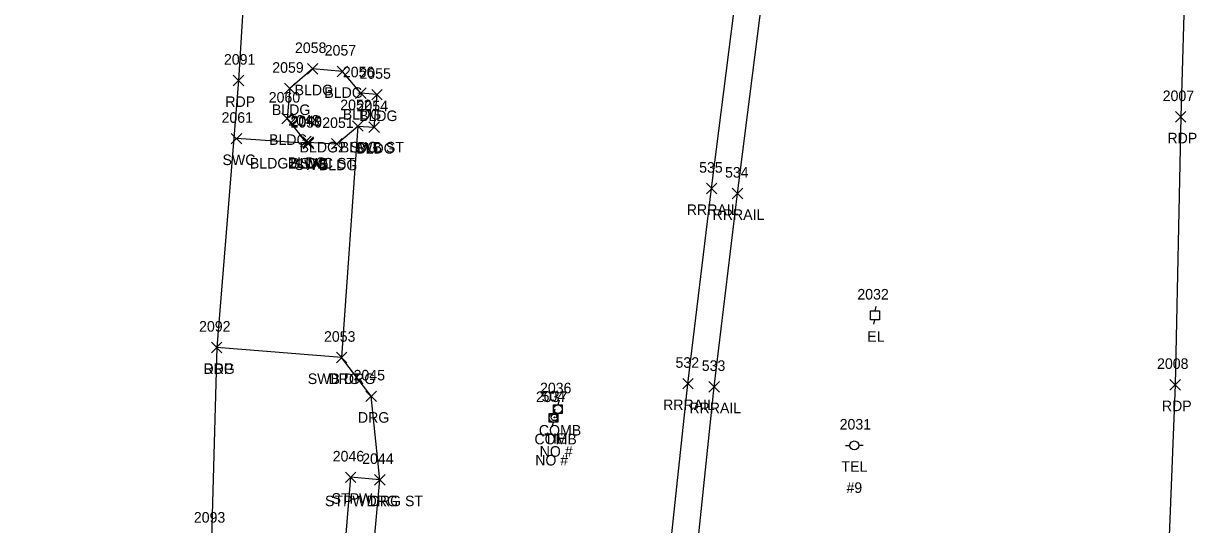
# Model space of a CAD drawing. Extents: x 1767353 to 1772625, y 740790 to 747702.
# Drawn here: x 1770045.2 to 1770267.3, y 741671.2 to 741766 of the extents above; entities that cross this region are included whole.
import ezdxf

# ---------------------------------------------------------------- set-up
doc = ezdxf.new("R2010")
doc.units = 0
for name, color, linetype in [('C_A', 7, 'Continuous'), ('C_I', 7, 'Continuous'), ('CBP', 7, 'Continuous'), ('L_A', 7, 'Continuous'), ('L_I', 7, 'Continuous'), ('L_TIC', 7, 'Continuous'), ('LBC', 7, 'Continuous'), ('LBF', 7, 'Continuous'), ('P_A', 7, 'Continuous'), ('P_I', 7, 'Continuous'), ('P_TIC', 7, 'Continuous'), ('PET', 7, 'Continuous'), ('R_A', 7, 'Continuous'), ('R_I', 7, 'Continuous'), ('R_TIC', 7, 'Continuous'), ('RDG', 7, 'Continuous'), ('RR', 7, 'Continuous'), ('RSW', 7, 'Continuous'), ('U_A', 7, 'Continuous'), ('U_C', 7, 'Continuous'), ('U_I', 7, 'Continuous'), ('UEPT', 7, 'Continuous'), ('UP', 7, 'Continuous')]:
    doc.layers.add(name, color=color, linetype=linetype)

msp = doc.modelspace()

# ---------------------------------------------------------------- linework, layer by layer
at = {"layer": 'CBP'}
for radius in [0.625, 0.0833]:
    msp.add_circle((1770145.73, 741691.51), radius, dxfattribs=at)
at = {"layer": 'L_TIC'}
for points in [[(1770098.93, 741756.44), (1770100.93, 741758.44)], [(1770100.93, 741756.44), (1770098.93, 741758.44)], [(1770104.56, 741755.96), (1770106.56, 741757.96)], [(1770106.56, 741755.96), (1770104.56, 741757.96)], [(1770094.63, 741752.71), (1770096.63, 741754.71)], [(1770096.63, 741752.71), (1770094.63, 741754.71)], [(1770108.05, 741751.85), (1770110.05, 741753.85)], [(1770110.05, 741751.85), (1770108.05, 741753.85)], [(1770111.13, 741751.57), (1770113.13, 741753.57)], [(1770113.13, 741751.57), (1770111.13, 741753.57)], [(1770094.09, 741747.06), (1770096.09, 741749.06)], [(1770096.09, 741747.06), (1770094.09, 741749.06)], [(1770094.09, 741747.06), (1770096.09, 741749.06)], [(1770096.09, 741747.06), (1770094.09, 741749.06)], [(1770107.49, 741745.63), (1770109.49, 741747.63)], [(1770109.49, 741745.63), (1770107.49, 741747.63)], [(1770110.59, 741745.42), (1770112.59, 741747.42)], [(1770112.59, 741745.42), (1770110.59, 741747.42)], [(1770097.66, 741742.7), (1770099.66, 741744.7)], [(1770099.66, 741742.7), (1770097.66, 741744.7)], [(1770097.66, 741742.7), (1770099.66, 741744.7)], [(1770099.66, 741742.7), (1770097.66, 741744.7)], [(1770098.08, 741742.59), (1770100.08, 741744.59)], [(1770100.08, 741742.59), (1770098.08, 741744.59)], [(1770103.53, 741742.26), (1770105.53, 741744.26)], [(1770105.53, 741742.26), (1770103.53, 741744.26)], [(1770106.13, 741679.16), (1770108.13, 741681.16)], [(1770108.13, 741679.16), (1770106.13, 741681.16)], [(1770111.66, 741678.69), (1770113.66, 741680.69)], [(1770113.66, 741678.69), (1770111.66, 741680.69)]]:
    msp.add_lwpolyline(points, dxfattribs=at)
at = {"layer": 'LBC'}
for points in [[(1770098.66, 741743.7), (1770099.08, 741743.59), (1770104.53, 741743.26), (1770108.49, 741746.63), (1770111.59, 741746.42), (1770112.13, 741752.57), (1770109.05, 741752.85), (1770105.56, 741756.96), (1770099.93, 741757.44), (1770095.63, 741753.71), (1770095.09, 741748.06)], [(1770098.66, 741743.7), (1770095.09, 741748.06)]]:
    msp.add_lwpolyline(points, dxfattribs=at)
at = {"layer": 'LBF'}
msp.add_lwpolyline([(1770109.99, 741650.55), (1770112.66, 741679.69), (1770107.13, 741680.16), (1770104.69, 741650.97)], dxfattribs=at)
at = {"layer": 'P_TIC'}
for points in [[(1770084.91, 741754.24), (1770086.91, 741756.24)], [(1770086.91, 741754.24), (1770084.91, 741756.24)], [(1770263.31, 741747.35), (1770265.31, 741749.35)], [(1770265.31, 741747.35), (1770263.31, 741749.35)], [(1770080.77, 741703.72), (1770082.77, 741705.72)], [(1770082.77, 741703.72), (1770080.77, 741705.72)], [(1770262.25, 741696.67), (1770264.25, 741698.67)], [(1770264.25, 741696.67), (1770262.25, 741698.67)]]:
    msp.add_lwpolyline(points, dxfattribs=at)
at = {"layer": 'PET'}
for points in [[(1770086.36, 741896.23), (1770087.49, 741787.65), (1770087.53, 741783.15), (1770087.13, 741775.79), (1770085.91, 741755.24), (1770081.77, 741704.72), (1770080.78, 741668.58), (1770077.45, 741606.56), (1770073.71, 741567.99), (1770067.82, 741517.29), (1770065.02, 741495.1), (1770064.65, 741473.85), (1770058.3, 741423.48), (1770050.58, 741368.28), (1770045.18, 741323.67)], [(1770229.78, 741893.6), (1770250.07, 741887.1), (1770256.68, 741881.35), (1770263.49, 741873.94), (1770265.43, 741863.52), (1770266.15, 741845.69), (1770265.98, 741804.45), (1770264.31, 741748.35), (1770263.25, 741697.67), (1770261.51, 741653.19), (1770259.69, 741610.34)]]:
    msp.add_lwpolyline(points, dxfattribs=at)
at = {"layer": 'R_TIC'}
for points in [[(1770107.49, 741745.63), (1770109.49, 741747.63)], [(1770109.49, 741745.63), (1770107.49, 741747.63)], [(1770084.51, 741743.24), (1770086.51, 741745.24)], [(1770086.51, 741743.24), (1770084.51, 741745.24)], [(1770098.08, 741742.59), (1770100.08, 741744.59)], [(1770100.08, 741742.59), (1770098.08, 741744.59)], [(1770098.17, 741742.33), (1770100.17, 741744.33)], [(1770100.17, 741742.33), (1770098.17, 741744.33)], [(1770174.49, 741733.8), (1770176.49, 741735.8)], [(1770176.49, 741733.8), (1770174.49, 741735.8)], [(1770179.38, 741732.87), (1770181.38, 741734.87)], [(1770181.38, 741732.87), (1770179.38, 741734.87)], [(1770080.77, 741703.72), (1770082.77, 741705.72)], [(1770082.77, 741703.72), (1770080.77, 741705.72)], [(1770104.43, 741701.81), (1770106.43, 741703.81)], [(1770106.43, 741701.81), (1770104.43, 741703.81)], [(1770104.43, 741701.81), (1770106.43, 741703.81)], [(1770106.43, 741701.81), (1770104.43, 741703.81)], [(1770170.01, 741696.88), (1770172.01, 741698.88)], [(1770172.01, 741696.88), (1770170.01, 741698.88)], [(1770110.03, 741694.49), (1770112.03, 741696.49)], [(1770112.03, 741694.49), (1770110.03, 741696.49)], [(1770174.98, 741696.29), (1770176.98, 741698.29)], [(1770176.98, 741696.29), (1770174.98, 741698.29)], [(1770111.66, 741678.69), (1770113.66, 741680.69)], [(1770113.66, 741678.69), (1770111.66, 741680.69)]]:
    msp.add_lwpolyline(points, dxfattribs=at)
at = {"layer": 'RDG'}
msp.add_lwpolyline([(1770112.66, 741679.69), (1770111.03, 741695.49), (1770105.43, 741702.81), (1770081.77, 741704.72)], dxfattribs=at)
at = {"layer": 'RR'}
for points in [[(1770158.18, 741192.17), (1770156.33, 741234.55), (1770154.66, 741279.77), (1770153.5, 741326.69), (1770153.07, 741379.82), (1770153.42, 741422.94), (1770154.43, 741466.02), (1770156.03, 741508.16), (1770157.87, 741545.07), (1770160.69, 741586.39), (1770163.59, 741622.82), (1770166.84, 741658.9), (1770171.01, 741697.88), (1770175.49, 741734.8), (1770180.59, 741775.05), (1770185.91, 741810.5), (1770192.47, 741851.32), (1770197.89, 741882.78), (1770201.13, 741901.96), (1770208.66, 741941.8), (1770211.54, 741956.24), (1770217.02, 741983.21), (1770222.11, 742006.18)], [(1770163.08, 741192.31), (1770161.21, 741234.64), (1770159.62, 741280.6), (1770158.4, 741326.37), (1770158.03, 741379.87), (1770158.37, 741422.76), (1770159.48, 741466.41), (1770160.97, 741507.07), (1770162.92, 741544.79), (1770165.6, 741585.33), (1770168.59, 741623.26), (1770171.89, 741657.97), (1770175.98, 741697.29), (1770180.38, 741733.87), (1770185.58, 741774.59), (1770190.55, 741808.84), (1770197.31, 741850.84), (1770202.43, 741880.83), (1770205.99, 741900.79), (1770213.55, 741940.61), (1770216.39, 741955.4), (1770221.78, 741982.04), (1770226.9, 742005.14)]]:
    msp.add_lwpolyline(points, dxfattribs=at)
at = {"layer": 'RSW'}
for points in [[(1770108.49, 741746.63), (1770105.43, 741702.81)], [(1770099.08, 741743.59), (1770099.17, 741743.33), (1770085.51, 741744.24)]]:
    msp.add_lwpolyline(points, dxfattribs=at)
at = {"layer": 'UEPT'}
for p, q in [((1770206.59, 741712.46), (1770206.42, 741711.63)), ((1770205.59, 741709.96), (1770205.59, 741711.63)), ((1770205.59, 741711.63), (1770207.25, 741711.63)), ((1770207.25, 741709.96), (1770205.59, 741709.96)), ((1770206.17, 741709.13), (1770206.42, 741709.96)), ((1770206.42, 741710.8), (1770206.42, 741710.8)), ((1770207.25, 741711.63), (1770207.25, 741709.96))]:
    msp.add_line(p, q, dxfattribs=at)
at = {"layer": 'UP'}
for p, q in [((1770146.63, 741694.73), (1770146.38, 741693.9)), ((1770144.71, 741690.57), (1770144.71, 741692.24)), ((1770144.71, 741692.24), (1770146.38, 741692.24)), ((1770145.55, 741692.23), (1770145.55, 741693.9)), ((1770145.55, 741693.9), (1770147.21, 741693.9)), ((1770145.8, 741693.07), (1770145.55, 741692.24)), ((1770147.21, 741692.23), (1770145.55, 741692.23)), ((1770146.13, 741691.4), (1770146.38, 741692.23)), ((1770146.38, 741693.06), (1770146.38, 741693.06)), ((1770146.38, 741692.24), (1770146.38, 741690.57)), ((1770147.21, 741693.9), (1770147.21, 741692.23)), ((1770146.38, 741690.57), (1770144.71, 741690.57)), ((1770145.3, 741689.74), (1770145.55, 741690.57)), ((1770145.55, 741691.4), (1770145.55, 741691.4)), ((1770200.84, 741686.2), (1770201.66, 741686.2)), ((1770202.5, 741686.2), (1770202.5, 741686.2)), ((1770204.16, 741686.2), (1770203.33, 741686.2)), ((1770203.33, 741686.2), (1770203.33, 741686.2)), ((1770204.16, 741686.2), (1770204.16, 741686.2))]:
    msp.add_line(p, q, dxfattribs=at)
for centre in [(1770145.55, 741691.4), (1770146.38, 741693.06), (1770202.5, 741686.2)]:
    msp.add_circle(centre, 0.833, dxfattribs=at)

# ---------------------------------------------------------------- texts
at = {"layer": 'C_A'}
msp.add_text('TIE', height=2, dxfattribs=at).set_placement((1770143.8, 741686.51))
at = {"layer": 'C_I'}
msp.add_text('504', height=2, dxfattribs=at).set_placement((1770143.29, 741694.51))
at = {"layer": 'L_A'}
for s, p in [('BLDG', (1770096.52, 741752.44)), ('BLDG', (1770102.15, 741751.96)), ('BLDG', (1770092.22, 741748.71)), ('BLDG', (1770105.65, 741747.85)), ('BLDG', (1770108.72, 741747.57)), ('BLDG', (1770091.68, 741743.06)), ('BLDG', (1770091.68, 741743.06)), ('BLDG', (1770105.08, 741741.63)), ('BLDG', (1770108.18, 741741.42)), ('BLDG', (1770095.25, 741738.7)), ('BLDG', (1770095.25, 741738.7)), ('BLDG', (1770095.67, 741738.59)), ('BLDG', (1770101.12, 741738.26)), ('STPW DRG ST', (1770102.27, 741674.69)), ('STPW', (1770103.52, 741675.16))]:
    msp.add_text(s, height=2, dxfattribs=at).set_placement(p)
at = {"layer": 'L_I'}
for s, p in [('2058', (1770096.59, 741760.44)), ('2057', (1770102.22, 741759.96)), ('2059', (1770092.29, 741756.71)), ('2056', (1770105.66, 741755.85)), ('2055', (1770108.8, 741755.57)), ('2060', (1770091.62, 741751.06)), ('2060', (1770091.62, 741751.06)), ('2052', (1770105.16, 741749.63)), ('2054', (1770108.25, 741749.42)), ('2048', (1770095.32, 741746.7)), ('2048', (1770095.32, 741746.7)), ('2049', (1770095.74, 741746.59)), ('2051', (1770101.75, 741746.26)), ('2046', (1770103.74, 741683.16)), ('2044', (1770109.32, 741682.69))]:
    msp.add_text(s, height=2, dxfattribs=at).set_placement(p)
at = {"layer": 'P_A'}
for p in [(1770083.4, 741750.24), (1770261.8, 741743.35), (1770079.25, 741699.72), (1770260.74, 741692.67)]:
    msp.add_text('RDP', height=2, dxfattribs=at).set_placement(p)
at = {"layer": 'P_I'}
for s, p in [('2091', (1770083.14, 741758.24)), ('2007', (1770260.9, 741751.35)), ('2092', (1770078.43, 741707.72)), ('2008', (1770259.83, 741700.67)), ('2093', (1770077.44, 741671.58))]:
    msp.add_text(s, height=2, dxfattribs=at).set_placement(p)
at = {"layer": 'R_A'}
for s, p in [('BLDG2 SWB ST', (1770097.46, 741741.63)), ('SWC', (1770082.87, 741739.24)), ('BLDG2 SWC ST', (1770088.05, 741738.59)), ('SWC', (1770096.53, 741738.33)), ('RRRAIL', (1770170.78, 741729.8)), ('RRRAIL', (1770175.67, 741728.87)), ('DRG', (1770079.25, 741699.72)), ('SWB DRG', (1770099.01, 741697.81)), ('DRG', (1770102.92, 741697.81)), ('RRRAIL', (1770166.3, 741692.88)), ('RRRAIL', (1770171.27, 741692.29)), ('DRG', (1770108.51, 741690.49)), ('DRG', (1770110.14, 741674.69))]:
    msp.add_text(s, height=2, dxfattribs=at).set_placement(p)
at = {"layer": 'R_I'}
for s, p in [('2052', (1770105.16, 741749.63)), ('2061', (1770082.69, 741747.24)), ('2049', (1770095.74, 741746.59)), ('2050', (1770095.74, 741746.33)), ('535', (1770173.12, 741737.8)), ('534', (1770178.02, 741736.87)), ('2092', (1770078.43, 741707.72)), ('2053', (1770102.09, 741705.81)), ('2053', (1770102.09, 741705.81)), ('532', (1770168.65, 741700.88)), ('533', (1770173.62, 741700.29)), ('2045', (1770107.69, 741698.49)), ('2044', (1770109.32, 741682.69))]:
    msp.add_text(s, height=2, dxfattribs=at).set_placement(p)
at = {"layer": 'U_A'}
for s, p in [('EL', (1770204.96, 741705.8)), ('COMB', (1770142.77, 741688.06)), ('COMB', (1770141.93, 741686.4)), ('TEL', (1770200.06, 741681.2))]:
    msp.add_text(s, height=2, dxfattribs=at).set_placement(p)
at = {"layer": 'U_C'}
for s, p in [('NO #', (1770142.92, 741684.06)), ('NO #', (1770142.08, 741682.4)), ('#9', (1770201.02, 741677.2))]:
    msp.add_text(s, height=2, dxfattribs=at).set_placement(p)
at = {"layer": 'U_I'}
for s, p in [('2032', (1770203.08, 741713.8)), ('2037', (1770142.21, 741694.4)), ('2036', (1770142.99, 741696.06)), ('2031', (1770199.73, 741689.2))]:
    msp.add_text(s, height=2, dxfattribs=at).set_placement(p)

doc.saveas('drawing.dxf')
